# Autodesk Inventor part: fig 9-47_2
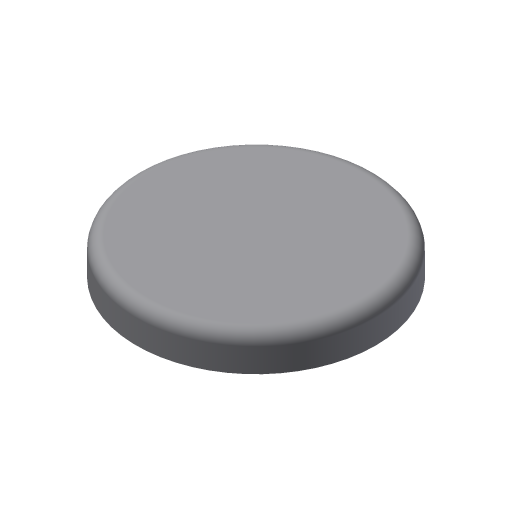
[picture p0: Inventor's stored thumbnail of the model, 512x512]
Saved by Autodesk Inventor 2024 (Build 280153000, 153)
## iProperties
Created: 2013-03
Part Number: fig 9-47_2
Material: Generic
Document SubType Name: Modeling
Designer: CADCIM
Density: 1 g/cm^3
Appearance: Default
Author: CADCIM
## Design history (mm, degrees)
sketch "Sketch1"
  geometry: C1 r 2.5 at (0, 0); 1 further point
  constraints: 1 centre point, 1 coincident
  dimensions: "d0" = 5 diameter of C1
extrude "Extrusion1" new body sketch "Sketch1" distance "d2" = 0.75; taper "d3" = 0 deg
fillet "Fillet1" dims "d4" = 0.25
body "Solid1"
